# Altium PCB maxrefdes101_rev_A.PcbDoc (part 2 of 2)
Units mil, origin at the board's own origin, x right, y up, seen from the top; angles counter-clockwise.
Board outline 1192.91 x 1079.23 mil, 4 copper layers (Top Layer, Power Plane, Ground Plane, Bottom Layer), stack 32.372 mil thick; 87 components, 63 nets, 389 pads, 163 vias.
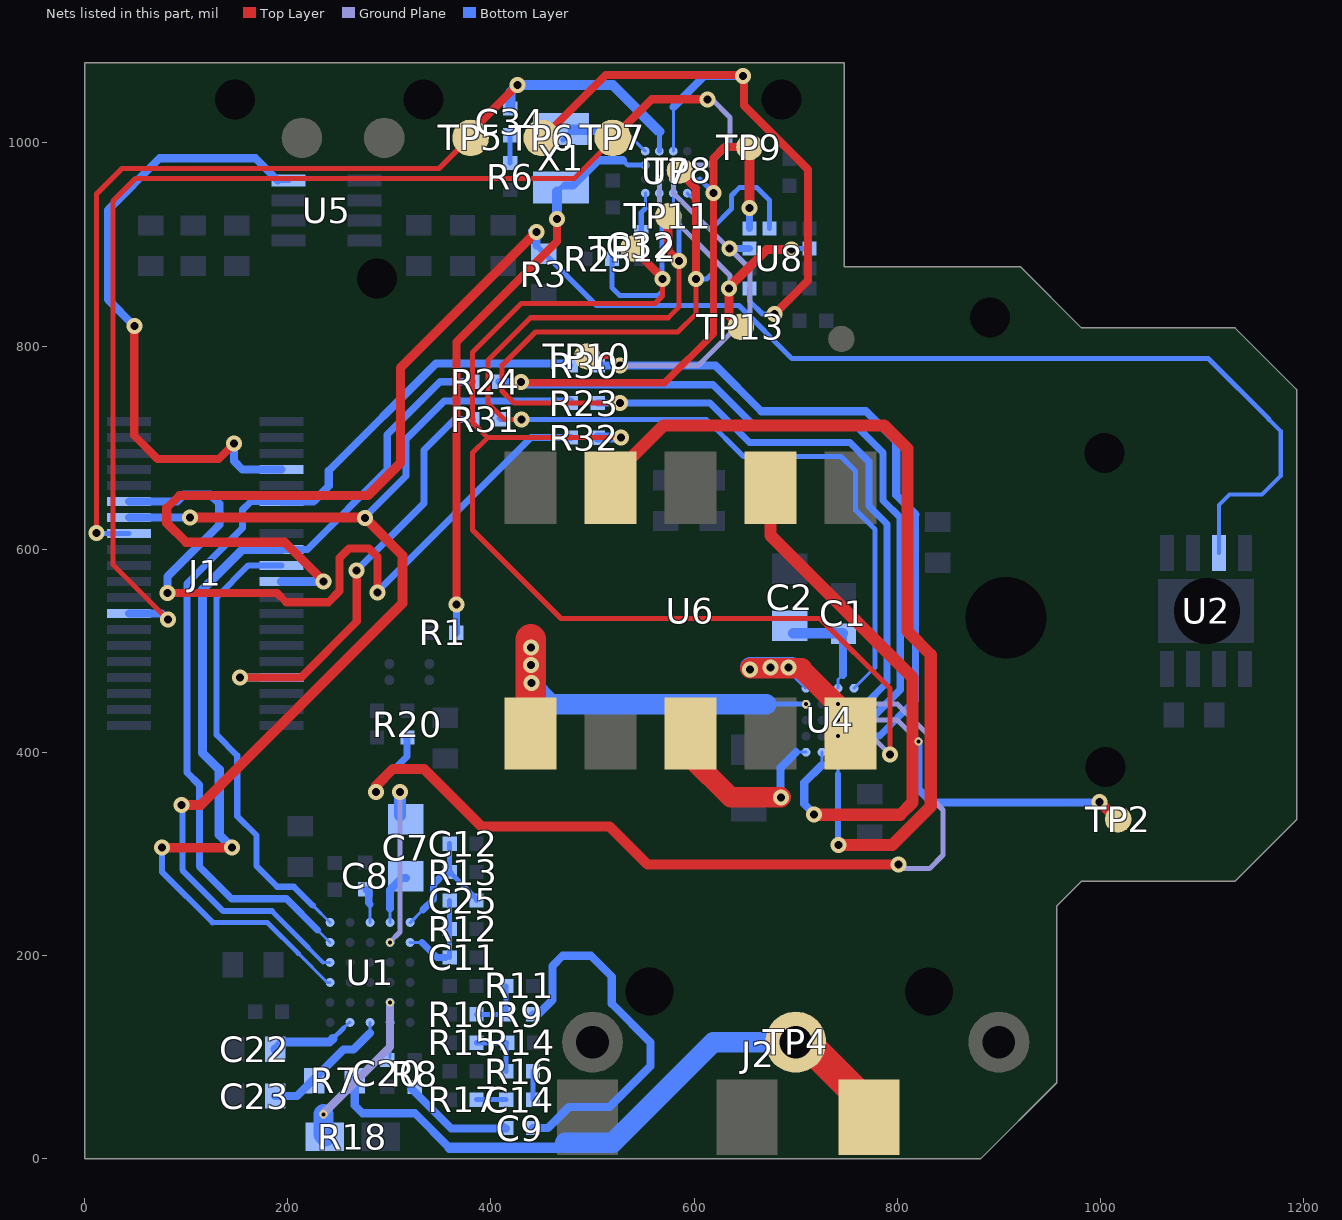
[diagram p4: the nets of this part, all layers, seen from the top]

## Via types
v1: diameter 15.75, hole 7.87, Top Layer to Bottom Layer, tented both sides, 114 vias
v2: diameter 8, hole 4, Ground Plane to Bottom Layer, 23 vias
v3: diameter 8, hole 4, Ground Plane to Bottom Layer, tented bottom, 14 vias
v4: diameter 11.81, hole 5.91, Ground Plane to Bottom Layer, tented bottom, 11 vias
v5: diameter 15.75/15.75/15.75/15.75 (per signal layer), hole 7.87, Top Layer to Bottom Layer, tented both sides, 1 vias

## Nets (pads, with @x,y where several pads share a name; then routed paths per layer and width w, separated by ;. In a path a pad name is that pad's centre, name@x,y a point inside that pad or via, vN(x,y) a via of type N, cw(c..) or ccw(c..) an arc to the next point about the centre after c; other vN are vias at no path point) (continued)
LED1: U4.D1 U6.3 | length 181.9
  Top Layer w20: U6.3@596.46,418.61 596.46,395.54 636,356 v1(685.39,356)
  Bottom Layer w3: 700.39,400.39 U4.D1@710.14,400.39
  Bottom Layer w8: v1@685,363 685,385 700.39,400.39
LED2_RESERVED: U4.C1 U6.7 | length 540.7
  Top Layer w12: U6.7@675.2,660.62 675.2,613.8 815,474 815,351 802.89,338.89 v1(717.89,338.89)
  Bottom Layer w3: 725.89,387.89 U4.C1@725.89,400.39
  Bottom Layer w8: v1@717.37,340.35 708.39,349.32 708.39,370.39 725.89,387.89
LED3_RESERVED: U4.B1 U6.9 | length 891.2
  Top Layer w5: U6.9@517.72,660.62 U6.9@517.72,669.72
  Top Layer w12: U6.9@517.72,669.72 570,722 787,722 810,699 810,519.37 833,496.37 833,347 795,309 v1(742,309)
  Bottom Layer w3: 741.64,378.7 U4.B1@741.64,399.39
  Bottom Layer w6: v1@741.64,309 741.64,378.7
LVL_SHIFT_PWDN: J1.7 U5.4 | length 622.2
  Top Layer w8: v1(49,820) 49,712 72,689 132.11,689 v1(147.12,704)
  Bottom Layer w5: U5.4@190.17,963.06 U5.4@201,963.06
  Bottom Layer w8: v1(49,820) 23,846 23,934 74,985 168.23,985 U5.4@190.17,963.06 ; v1(147.12,704) 147.12,686.88 155.24,678.76 J1.7@194,678.76
NetC1_1: C1.1 C2.1 U4.B5 | length 105
  Bottom Layer w3: U4.B5@741.64,463.38 741.64,471.87 746.39,476.62
  Bottom Layer w8: 746.39,476.62 C1.1@746.39,517.39
  Bottom Layer w10: C2.1@697.39,517.39 C1.1@746.39,517.39
NetC7_1: C7.1 U1.B6 | length 52.5
  Bottom Layer w3: U1.B6@300.7,232.81 300.7,246.48
  Bottom Layer w8: 300.7,246.48 300.7,264.83 312.26,276.39 C7.1@316.39,276.39
NetC7_2: C7.2 U1.B5 | length 175.5
  Ground Plane w5: v2@300.55,213.29 310.64,223.38 v1(310.64,361.39)
  Bottom Layer w12: C7.2@310.64,338.14 v1(310.64,361.39)
  other v2: 300.7,213.13
NetC8_1: C8.1 U1.C6 | length 34.3
  Bottom Layer w3: U1.C6@281.02,232.81 281.02,250.76
  Bottom Layer w7: C8.1@276.89,265.39 279.78,262.5 279.78,252 281.02,250.76
NetC9_1: C9.1 R9.1 | length 374.3
  Bottom Layer w8: C9.1@441.39,30.39 456.12,30.39 476.73,51 516.66,51 557,91.34 557,114.85 519,152.85 519,179.41 498.41,200 470.62,200 460.67,190.06 460.67,156.54 446.52,142.39 R9.1@441.39,142.39
NetC9_2: C9.2 R8.2 | length 113.3
  Bottom Layer w5: C9.2@412,33.39 C9.2@415,30.39
  Bottom Layer w8: R8.2@322.1,68.9 361,30 C9.2@415,30
NetC11_1: C11.1 C25.1 R12.1 U1.A5 | length 97.1
  Bottom Layer w3: U1.A5@320.39,213.13 332.18,213.13
  Bottom Layer w5: C11.1@359.39,198.39 R12.1@359.39,226.39 C25.1@359.39,254.39
  Bottom Layer w7: 332.18,213.13 346.92,198.39 C11.1@355.39,198.39
NetC12_1: C12.1 C25.2 R13.1 U1.A6 | length 135.7
  Bottom Layer w3: U1.A6@320.6,232.6 333,245
  Bottom Layer w5: C12.1@359.39,310.39 R13.1@359.39,282.39 385.78,256 C25.2@385.78,254.39
  Bottom Layer w7: 333,245 343.39,255.39 343.39,270.39 354.39,281.39 R13.1@360.39,281.39
NetC14_1: C14.1 R16.1 | length 28
  Bottom Layer w5: C14.1@441.39,58.39 R16.1@441.39,86.39
NetC14_2: C14.2 R17.2 | length 29.2
  Bottom Layer w5: R17.2@385.78,58.39 C14.2@415,58.39
NetC20_2: C20.2 U1.B1 | length 34.3
  Bottom Layer w3: C20.2@300.7,100.14 U1.B1@300.7,134.39
NetC22_2: C22.2 U1.D1 | length 84.6
  Bottom Layer w3: 255.04,129.04 260.39,134.39 U1.D1@261.33,134.39
  Bottom Layer w5: 244.35,118.35 255.04,129.04
  Bottom Layer w9: C22.2@187.62,108 194.62,115 241,115 244.35,118.35
NetC23_2: C23.2 R7.2 U1.C1 | length 129.5
  Bottom Layer w3: 281.02,124.02 U1.C1@281.02,134.39
  Bottom Layer w8: C23.2@187.62,62 209.16,62 254.97,107.81 264.81,107.81 281.02,124.02
NetC32_1: C32.1 U7.A4 | length 39.9
  Bottom Layer w3: 552,935.5 U7.A4@552,950.66
  Bottom Layer w5: C32.1@548,912.39 548,931.5 552,935.5
NetC34_2: C34.2 R6.1 | length 27.4
  Bottom Layer w5: R6.1@419,980.19 C34.2@419,1007.61
NetR1_2: R1.2 U7.A2 X1.2 | length 574
  Top Layer w8: v1(366,546) 366,804 465,903 v1(465,925)
  Bottom Layer w5: X1.2@465,952 X1.2@469,956 ; 530,983 534.78,978.22 U7.A2@552,978.22
  Bottom Layer w7: R1.2@365.97,518 v1@365.97,547.97
  Bottom Layer w8: X1.2@473,958 481,958 506,983 530,983
  Bottom Layer w10: v1(465,925) X1.2@465,952
NetR9_2: R9.2 R10.2 R11.2 | length 57.2
  Bottom Layer w5: R10.2@385.78,142.39 R9.2@415,142.39 R11.2@415,170.39
NetR14_1: R14.1 R15.2 R16.2 | length 57.2
  Bottom Layer w5: R15.2@385.78,114.39 R14.1@415.39,114.39 ; R16.2@415,86.39 R14.1@415,114
NetR18_1: R18.1 U1.B2 | length 160
  Ground Plane w8: v3@234.86,44.32 300.7,110.17 v2(300.7,154.07)
  Bottom Layer w5: R18.1@236.46,22 R18.1@237,22.54
  Bottom Layer w20: v3(235.2,43.98) 235.2,24.33 R18.1@237,22.54
NetR20_2: R20.2 U4.B4 | length 914.2
  Top Layer w10: v1(287,361) 287,367.39 303.61,384 334,384 390.61,327.39 516.61,327.39 554,290 v1(801,290)
  Ground Plane w5: v2(741.64,447.63) 800.19,447.63 833,414.82 833,355.39 845,343.39 845,299.11 831.65,285.76 805.24,285.76 v1(801,290)
  Bottom Layer w7: v1(287,361) 287,365.6 317.56,396.16 317.56,414.25 R20.2@316,415.81
  Bottom Layer w8: v1@798,290 v1(801,290)
NetTP2_TP: TP2.TP U4.B3 | length 343.8
  Top Layer w8: TP2.TP@1016,334.39 TP2.TP@1017.39,334.39
  Top Layer w10: v1(999.19,351.19) TP2.TP@1016,334.39
  Ground Plane w5: v2(741.64,431.89) 800.11,431.89 v3(821,411)
  Bottom Layer w8: v3(821,411) 821,363.89 833.89,351 v1@999.19,351
NetU7_A1: U7.A1 X1.1 | length 93.8
  Bottom Layer w3: 531,1013 U7.A1@552,992
  Bottom Layer w5: X1.1@471,1003 X1.1@481,1013
  Bottom Layer w10: X1.1@481,1013 531,1013
PD1: U4.D5 U6.5 | length 203.4
  Top Layer w5: v1@659,483 v1@660.15,481.85 ; U6.5@753.94,418.61 U6.5@753.94,434.06
  Top Layer w20: v1@655.15,483 706.15,483 ; 706.15,481.85 U6.5@753.94,434.06
  Bottom Layer w3: v1@691.32,482 709.93,463.39 U4.D5@710.14,463.38
  Bottom Layer w20: v1@655.16,484 v1@696.32,484
  other v1: 655.16,482 675,484 693,484
PD2: U4.D4 U6.1 | length 439.2
  Top Layer w30: U6.1@439.11,421.77 439.11,511.37
  Bottom Layer w5: v1(439.64,503.23) v1@439.95,502.92 ; 671.11,447.63 v2(710.14,447.63)
  Bottom Layer w20: v1(439.64,503.23) 439.64,467.1 459.11,447.63 671.11,447.63 ; v1(439.95,468.42) v1@439.95,502.92
  other v1: 439.64,486.23
PPG_INT: J1.12 R32.2 | length 748.9
  Top Layer w8: v1(81.77,557) 189.61,557 198.61,548 240,548 251,559 251,591.61 260.39,601 280,601 288.26,592.74 v1(288.26,557.62)
  Bottom Layer w7: v1(288.26,557.62) 287.24,557.62 439.62,710 R32.2@478.81,710
  Bottom Layer w8: J1.12@44,647.26 91.26,647.26 98,654 123.6,654 132.6,645 132.6,624.11 81.77,573.27 81.77,558.87 v1@81,558.11
PS00_ACCEL_CS: TP6.TP U7.C1 U8.10 | length 663.4
  Top Layer w8: TP6.TP@451,1005 513,1067 645,1067 649,1063 649,1037 712,974 712,864.61 v1(679,831.61)
  Bottom Layer w3: U7.C1@579.56,992 579.56,1035.56
  Bottom Layer w5: U8.10@654.39,856.94 654.39,844.61 667.39,831.61 v1(679,831.61)
  Bottom Layer w8: 579.56,1035.56 610,1066 v1(648,1066)
PS01_MFIO: J1.26 TP7.TP U7.C2 | length 1223.2
  Top Layer w5: v5@81.5,531.5 28,585 28,942.88 50.12,965 482,965 519,1002 TP7.TP@519,1006
  Top Layer w8: TP7.TP@520,1005 558,1043 609,1043 v1@611,1045
  Ground Plane w5: v2(579.56,978.22) 614.25,978.22 635.39,999.35 635.39,1025.21 617.3,1043.3 v1@613,1039
  Bottom Layer w8: J1.26@44,537.02 75.98,537.02 v5(82,531)
  other v1: 613,1043
PS04_SPI0_MISO: R24.1 TP9.TP U4.A3 U7.D3 U8.1 | length 1238.1
  Top Layer w5: v1@651,936 654.39,939.39 654.39,937.34 v1(654.39,936)
  Top Layer w7: v1@431.81,764 571,764 619,812 v1(619,951)
  Top Layer w8: v1(619,951) 618,951 619,952 619,985 630,996 TP9.TP@654.39,996 ; v1@653.36,938.36 v1@654.39,937.34
  Top Layer w10: v1@654.39,939.39 TP9.TP@654.39,996
  Bottom Layer w3: U7.D3@593.34,964.44 605.83,964.44 ; U4.A3@757.39,431.89 772.89,431.89
  Bottom Layer w5: 605.83,964.44 v1@618,952.27
  Bottom Layer w7: R24.1@408.19,765 v1(429.81,765) ; v1@432.81,762 618.72,762 657.72,723 758.2,723 786,695.2 786,648.28 802.88,631.4 802.88,461.88 772.89,431.89 ; U8.1@654.39,916 v1(654.39,936)
PS05_SPI0_MOSI: R23.1 TP8.TP U4.A4 U7.D4 U8.2 | length 1379.9
  Top Layer w5: v1(527,744) 423,744 411,756 411,781 444,814 584,814 602,832 v1(602,866.2)
  Top Layer w8: TP8.TP@586.33,979 586.33,970.92 602,955.25 v1(602,866.2)
  Bottom Layer w3: U7.D4@593.34,950.66 601.39,942.61 ; U4.A4@757.39,447.63 768.63,447.63
  Bottom Layer w5: v1@598,867 v1@601.39,867 ; v1@601.39,866.2 v1@601.39,867 ; 601.39,911.12 v1@601.39,867 ; 601.39,942.61 v1@601.39,867 ; v1(602,866.2) 612.44,866.2 618.72,872.49 618.72,917.18 636.82,935.28 636.82,948.29 644.54,956 662,956 674.07,943.93 U8.2@674.07,916
  Bottom Layer w7: R23.1@505.19,744 615.63,744 654.54,705.1 753.42,705.1 772.23,686.29 772.23,642.77 790,625 790,469 768.63,447.63
PS06_SPI0_SCK: R30.1 TP10.TP U4.A2 U7.C3 U8.12 | length 1029.8
  Top Layer w5: TP10.TP@495,790 518.07,790 v1(527.07,781)
  Ground Plane w5: v1(527.07,781) 604.01,781 655,832 655,875.91 v1(634.84,896.07) ; v2(579.56,964.44) 579.56,950.9 v1@634.61,895.85
  Bottom Layer w3: U4.A2@757.39,416.14 770.64,416.14
  Bottom Layer w7: v1@634.84,896.31 U8.12@654.39,896.31 ; 770.39,416.39 782.39,416.39 818,452 818,634.51
  Bottom Layer w8: R30.1@506,781 v1(527.07,781) 621,781 666.06,735.94 769.06,735.94 799,706 799,653.51 818,634.51
PS07_PPG_CS: R31.1 TP11.TP U4.A5 U7.C4 | length 1060.9
  Top Layer w5: v1(430,728) 413,728 397,744 397,786 439,828 574.56,828 585,838.44 585,881.56 v1@581.56,885
  Top Layer w8: TP11.TP@574.56,928 574.56,894.44 v1(585,884)
  Bottom Layer w3: 579.56,934.76 U7.C4@579.56,950.66 ; U4.A5@757.39,463.38 778,483.99
  Bottom Layer w5: R31.1@408.19,729 409.2,728 612,728 648.65,691.35 744.49,691.35 759,676.83 759,638.74 778,619.74 778,483.99 ; 579.56,934.76 585,929.32 585,889 v1@580,884
PS08_PPG_INT: R25.2 R32.1 TP12.TP U4.B2 U7.B4 | length 1388.6
  Top Layer w5: v1(528,710) 397,710 ; v1(569,866.19) v1@569,867.07 ; v1@570.19,864.19 569,863 569,849.44 561.56,842 430,842 382,794 382,725 397,710 ; v1(793,398) 793,463 724,532 469,532 382,619 382,695 397,710
  Top Layer w8: TP12.TP@540,896.07 v1@569,867.07
  Ground Plane w5: v2(741.64,416.14) 774.86,416.14 v1(793,398)
  Bottom Layer w3: U7.B4@565.78,950.66 565.78,930.65 568.46,927.96
  Bottom Layer w5: R25.2@519.19,887 519.19,857.57 526.76,850 564.93,850 569,854.07 v1(569,866.19) ; 568.46,927.96 568.46,867.92 v1@569,867.39
  Bottom Layer w10: R32.1@505.19,710 v1(528,710)
PS09_ACCEL_INT: TP13.TP U7.B3 U8.5 | length 274.5
  Top Layer w9: TP13.TP@646,819 634.39,830.61 634.39,858.05 671.34,895 v1(696,895)
  Ground Plane w5: v2(565.78,964.44) 565.78,939.26 635.37,869.67 v1@635.37,856.94
  Bottom Layer w5: v1@696,896.31 U8.5@713.44,896.31
  other v1: 634.39,856.94
PS_RESET: C34.1 J1.16 TP5.TP U7.B1 | length 1028
  Top Layer w5: v1(11.73,616) 11.73,949.73 37,975 349,975 374.5,1000.5 TP5.TP@378.5,1000.5 ; v1(426,1057) v1@430,1057
  Top Layer w8: TP5.TP@376,1007 v1(426,1057)
  Bottom Layer w5: v1@16,615.76 J1.16@44,615.76 ; U7.B1@565.78,992 565.78,1011.22
  Bottom Layer w10: C34.1@419.26,1034 419.26,1050.26 v1(426,1057) 520,1057 565.78,1011.22
SPI_ECG_SS: J1.19 U1.E6 | length 453.2
  Bottom Layer w3: 224.8,249.38 225.09,249.38 U1.E6@241.65,232.81
  Bottom Layer w6: J1.19@194,584.27 161.34,584.27 130,552.93 130,417.39 150.39,397 150.39,337.39 169.39,318.39 169.39,288.19 189.58,268 206.17,268 224.8,249.38
SPI_MISO: J1.17 R24.2 U1.E3 | length 940.1
  Top Layer w9: v1(76.39,306.39) v1(145.4,306.39)
  Bottom Layer w3: 210.39,202.39 239.02,173.76 U1.E3@241.65,173.76
  Bottom Layer w5: 125.96,232.81 179.96,232.81 210.39,202.39
  Bottom Layer w6: v1(76.39,306.39) 76.39,282.39 125.96,232.81
  Bottom Layer w7: J1.17@194,600.02 219.38,600.02 297.96,678.6 297.96,712.96 350,765 R24.2@381.81,765
  Bottom Layer w9: v1(145.4,306.39) 132.6,319.19 132.6,383.25 116,399.85 116,560.39 155.63,600.02 J1.17@194,600.02
SPI_MOSI: J1.14 R23.2 U1.E4 | length 1151.2
  Top Layer w10: v1(95.39,348.39) 114.39,348.39 313,547 313,594 v1(276,631) ; v1(104,631.51) v1@276,631.51
  Bottom Layer w3: 234.82,193.44 U1.E4@241.65,193.44
  Bottom Layer w4: 220.39,207.87 234.82,193.44
  Bottom Layer w5: 184.26,244 220.39,207.87
  Bottom Layer w6: v1@96.39,346.39 96.39,284.39 136.78,244 184.26,244
  Bottom Layer w7: v1@276,628 276,631.8 316.39,672.19 316.39,708.39 354,746 R23.2@478.81,746
  Bottom Layer w8: J1.14@44,631.51 v1(104,631.51)
SPI_PPG_SS: J1.33 R31.2 | length 435.4
  Top Layer w8: v1(152.93,474) 213,474 268,529 v1@268,579.22
  Bottom Layer w7: v1(267.86,579.22) 334,645.36 334,697.75 364.25,728 R31.2@381.81,728
  Bottom Layer w8: v1@152.96,474.03 J1.33@194,474.03
SPI_SCLK: J1.11 R30.2 U1.E5 | length 929.1
  Bottom Layer w3: 229.39,225.39 U1.E5@241.65,213.13
  Bottom Layer w7: J1.11@194,647.26 163.79,647.26 155.63,639.1 155.63,621 101,566.37 101,380.33 113,368.33 113,287.78 144.66,256.12 198.66,256.12 229.39,225.39
  Bottom Layer w8: J1.11@194,647.26 225.26,647.26 240.39,662.39 240.39,677.39 346,783 475,783 R30.2@477,781
TEMP_OS: J1.21 R3.2 U2.3 | length 1764.6
  Top Layer w8: 81,640.61 93.39,653
  Top Layer w9: 81,640.61 81,626 100,607 197,607 236,568 v1@238.51,568 ; 93.39,653 279,653 311,685 311,778.61 v1(444.78,912.39)
  Bottom Layer w4: U2.3@1116.8,596.48 1116.8,643.8 1127,654 1159,654 1177.39,672.39 1177.39,716.61 1166,728
  Bottom Layer w5: v1@439.19,913.81 v1@446.58,913.81 ; R3.2@444.78,899.22 504,840 644.18,840 696.18,788 1106,788 1166,728
  Bottom Layer w8: R3.2@444.78,899.22 v1(444.78,912.39)
  Bottom Layer w9: J1.21@194,568.52 v1@238.51,568.52
  other v1: 235,568.52
VCM: J2.1 R7.1 TP4.TP | length 620.9
  Top Layer w30: TP4.TP@710,115 769,56 769,58 767,56 J2.1@767,42
  Bottom Layer w8: R7.1@266,77 266,52.76 273.76,45 325.13,45 359.13,11
  Bottom Layer w10: 359.13,11 468,11 473,16
  Bottom Layer w20: 473,16 520,16 619,115 TP4.TP@700,115
pads on no net: J1.1 J1.5 J1.6 J1.8 J1.15 J1.20 J1.22 J1.23 J1.27 J1.28 J1.29 J1.30 J1.31 J1.32 J1.34 J1.35 J1.36 J1.37 J2.0 U1. U1.C2 U2.9 U4. U6.6 U6.10 U7. U8.6

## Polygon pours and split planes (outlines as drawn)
1V8 on Power Plane "PLANE_1V8" (solid, pour order 4): 0,0 509.73,0.31 509.73,226.39 525.73,242.39 840,242.39 840,878.39 812.39,878.39 748,878.39 748,1078.23 0,1079.23
5V on Power Plane "PLANE_5V" (solid, remove dead copper, pour order 2): 57.98,702.77 157.75,603 476.24,603 710.51,368.74 710.51,344.48 735,320 776.26,320 804.43,348.17 804.43,465.09 620,649.51 620,718.21 548.83,789.39 320.57,789.39 256.77,725.59 226.19,725.59 175.78,776 82,776 57.98,751.98
GND on Ground Plane "PLANE_GROUND" (solid, remove dead copper, pour order 6): 0,0 772,0 836.39,64.39 836.39,1079.23 0,1079.23
GND on Bottom Layer "COMPONENT_GND" (solid, remove dead copper, pour order 8): 0,0 825,0 836,11 836,878.39 748.61,878.39 748,879 748,1079 0,1079

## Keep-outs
Keep-Out Layer:
  lines w1: 0,0 0,1079.23 748,1079.23 748,878.39 920.91,878.39 981.39,817.91 1132.39,817.91 1192.91,757.39 1192.91,333.91 1132.39,273.39 981.39,273.39 957,249 957,75 882,0 0,0 ; 752.39,881.39 1119.39,881.39 1119.39,1079.23 752.39,1079.23 752.39,881.39

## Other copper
Top Layer:
  text "Top Layer" at 2872,76 h60
Power Plane:
  pour cut-out: 836.39,0.31 836.39,1079.23 1192.91,1079.23 1192.91,714.39 1192.91,0
  text "Power Plane" at 2883,-21 h60
Ground Plane:
  pour cut-out: 748,878 748,1079 1119.39,1079 1119,1078.61 1119,881.39
  pour cut-out: 761,-0.17 761,166 835.39,166 835.39,1 836.39,0
  pour cut-out: 499,500.5 499,461.33 504.33,456 619.48,456 634.95,471.48 634.85,494.14 623.37,505.62 503.55,505.62
  text "Ground Plane" at 2878,-102 h60
Bottom Layer:
  pour cut-out: 838.48,367 838.48,712 837.48,713 1192,713 1192,367
  text "Bottom Layer" at 2882,-190 h60

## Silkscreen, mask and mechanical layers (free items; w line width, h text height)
Top Overlay:
  drawing of 1575 lines, arcs and shapes, not listed
  text "REV-A" at 70,846.46 h70 r90
  text "TM" at 240.49,823.56 h25 r90
  text "Top Silkscreen" at 2875,173 h60
  text "ECGP" at 521,165 h55 r90
  text "ECGN" at 918,165 h55 r90
  text "VCM" at 718,164 h55 r90
  text "MAXREFDES101#" at 70,27 h70 r90
Bottom Overlay:
  circle w10: c337,118 r4.47
  circle w10: c536,1031 r4.24
  circle w10: c631,929 r4.24
  circle w10: c801,382 r4.47
  text "Bottom Silkscreen" at 2883,-281 h60
Mechanical 1:
  drawing of 295 lines, arcs and shapes, not listed
  text "Layer" at 2963.09,1892 h60
  text "Name" at 3373,1892 h60
  text "Material" at 4302.74,1892 h60
  text "Thickness" at 5162.51,1892 h60
  text "Constant" at 5812.35,1892 h60
  text "Board Layer Stack" at 6382.21,1892 h60
  text "1" at 2963.09,1772 h60
  text "Top Overlay" at 3373,1772 h60
  text "2" at 2963.09,1652 h60
  text "Top Solder" at 3373,1652 h60
  text "Solder Resist" at 4302.74,1652 h60
  text "0.40mil" at 5162.51,1652 h60
  text "3.5" at 5812.35,1652 h60
  text "3" at 2963.09,1532 h60
  text "Top Layer" at 3373,1532 h60
  text "Copper" at 4302.74,1532 h60
  text "1.40mil" at 5162.51,1532 h60
  text "4" at 2963.09,1412 h60
  text "Dielectric1" at 3373,1412 h60
  text "FR-4" at 4302.74,1412 h60
  text "6.89mil" at 5162.51,1412 h60
  text "4.2" at 5812.35,1412 h60
  text "5" at 2963.09,1292 h60
  text "Power Plane" at 3373,1292 h60
  text "Copper" at 4302.74,1292 h60
  text "1.40mil" at 5162.51,1292 h60
  text "6" at 2963.09,1172 h60
  text "Dielectric2" at 3373,1172 h60
  text "FR-4" at 4302.74,1172 h60
  text "12.99mil" at 5162.51,1172 h60
  text "4.2" at 5812.35,1172 h60
  text "7" at 2963.09,1052 h60
  text "Ground Plane" at 3373,1052 h60
  text "Copper" at 4302.74,1052 h60
  text "1.40mil" at 5162.51,1052 h60
  text "8" at 2963.09,932 h60
  text "Dielectric5" at 3373,932 h60
  text "FR-4" at 4302.74,932 h60
  text "6.89mil" at 5162.51,932 h60
  text "4.2" at 5812.35,932 h60
  text "9" at 2963.09,812 h60
  text "Bottom Layer" at 3373,812 h60
  text "Copper" at 4302.74,812 h60
  text "1.40mil" at 5162.51,812 h60
  text "10" at 2963.09,692 h60
  text "Bottom Solder" at 3373,692 h60
  text "Solder Resist" at 4302.74,692 h60
  text "0.40mil" at 5162.51,692 h60
  text "3.5" at 5812.35,692 h60
  text "11" at 2963.09,572 h60
  text "Bottom Overlay" at 3373,572 h60
Mechanical 11:
  lines w1: 0,0 0,38 0,1079.23 748,1079.23 748,878.39 920.91,878.39 981.39,817.91 1132.39,817.91 1192.91,757.39 1192.91,333.91 1132.39,273.39 981.39,273.39 957,249 957,75 882,0 0,0
  text "Board Outline" at 2884,-371 h60
Mechanical 16:
  circle w25: c7712.68,-99.1 r158.12
  lines w5: -1405,1145 -1205,1145 ; -1397,3760 -1197,3760 ; -1397,6135 -1197,6135 ; 1095,-1230 1095,-1030 ; 1095,8070 1095,8270 ; 3595,-1230 3595,-1030 ; 3595,8070 3595,8270 ; 6095,-1230 6095,-1030 ; 6095,8070 6095,8270 ; 8595,-1230 8595,-1030 ; 8595,8070 8595,8270 ; 8895,-730 13395,-730 ; 8895,-430 13395,-430 ; 8895,-130 10395,-130 ; 10395,-1030 10395,-430 10395,170 ; 11095,-1230 11095,-1030 ; 11095,8070 11095,8270 ; 12495,-1030 12495,-430 ; 13395,1145 13595,1145 ; 13395,3520 13595,3520 ; 13395,5895 13595,5895 ; 8895,-1030 7495,-1030 7495,170 8895,170 ; 8895,-1030 13395,-1030 ; 8895,-1030 8895,170 ; 8895,170 10395,170 ; 10395,170 13395,170 13395,-1030 ; 13395,-1030 13395,8070 -1205,8070 -1205,-1030 13395,-1030 ; -1405,-1230 -1405,8270 13595,8270 13595,-1230 -1405,-1230
  text "1" at -173.66,8140 h70
  text "2" at 2322,8140 h70
  text "3" at 4811.34,8140 h70
  text "4" at 7318.01,8140 h70
  text "5" at 9817,8140 h70
  text "6" at 12322,8140 h70
  text "A" at -1330,6997 h70
  text "A" at 13470,6997 h70
  text "B" at -1322,4857 h70
  text "B" at 13470,4617 h70
  text "C" at -1330,2242 h70
  text "C" at 13470,2242 h70
  text "ENGINEER:" at 8945,70 h45
  text "TITLE:" at 10445,70 h45
  text "maxim" at 7927.69,-62.27 h225
  text "MAXREFDES101#" at 10544,-80 h118.11
  text "D" at -1330,-128 h70
  text "D" at 13470,-128 h70
  text "T" at 8717.69,-212.27 h100
  text "M" at 8767.69,-212.27 h100
  text "integrated" at 7927.69,-222.27 h225
  text "PCB DESIGNER:" at 8945,-225 h45
  text "Maxim Integrated" at 7602.69,-437.27 h80
  text "DATE:" at 8945,-530 h45
  text "PART NO.:" at 10445,-530 h45
  text "REV:" at 12545,-530 h45
  text "160 Rio Robles" at 7602.69,-592.27 h80
  text "A" at 12721,-633 h59.06
  text "4/5/2018" at 8976,-647 h59.06
  text "San Jose, CA 95134" at 7602.69,-707.27 h80
  text "FILE NAME:" at 8945,-830 h45
  text "DWG NO:" at 10445,-830 h45
  text "SCALE:" at 12545,-830 h45
  text "(408) 733-7600" at 7597.69,-852.27 h80
  text "MAXREFDES101_A" at 8995,-950 h59.06
  text "1" at -173.66,-1160 h70
  text "2" at 2322,-1160 h70
  text "3" at 4811.34,-1160 h70
  text "4" at 7318.01,-1160 h70
  text "5" at 9817,-1160 h70
  text "6" at 12322,-1160 h70
Drill Drawing:
  circle w10: c1222.78,3239.71 r33.17
  lines w10: 1189.61,2626.04 1206.2,2626.04 1206.2,2609.46 1239.37,2609.46 1239.37,2626.04 1255.96,2626.04 1255.96,2659.21 1239.37,2659.21 1239.37,2675.8 1206.2,2675.8 1206.2,2659.21 1189.61,2659.21 1189.61,2626.04 ; 1189.61,2758.73 1255.96,2758.73 1255.96,2825.07 1189.61,2825.07 1189.61,2758.73 ; 1189.61,2908 1222.78,2924.59 1255.96,2908 1239.37,2941.17 1255.96,2974.34 1222.78,2957.76 1189.61,2974.34 1206.2,2941.17 1189.61,2908 ; 1189.61,3073.86 1206.2,3073.86 1222.78,3057.27 1239.37,3073.86 1255.96,3073.86 1239.37,3090.44 1255.96,3107.03 1239.37,3107.03 1222.78,3123.61 1206.2,3107.03 1189.61,3107.03 1206.2,3090.44 1189.61,3073.86 ; 1189.61,3388.99 1222.78,3355.81 1255.96,3388.99 1222.78,3422.16 1189.61,3388.99 ; 1189.61,3571.43 1255.96,3571.43 1222.78,3505.09 1189.61,3571.43 ; 1189.61,3654.36 1255.96,3654.36 1255.96,3720.7 1189.61,3720.7 1189.61,3654.36 ; 1189.61,3803.63 1189.61,3820.21 1206.2,3836.8 1189.61,3853.39 1189.61,3869.97 1206.2,3869.97 1222.78,3853.39 1239.37,3869.97 1255.96,3869.97 1255.96,3853.39 1239.37,3836.8 1255.96,3820.21 1255.96,3803.63 1239.37,3803.63 1222.78,3820.21 1206.2,3803.63 1189.61,3803.63 ; 1202.88,3667.63 1242.69,3667.63 1242.69,3707.43 1202.88,3707.43 1202.88,3667.63
  lines w15: 1130.1,2564.68 12964.75,2564.68 ; 1130.1,3908.12 12964.75,3908.12 ; 1678.45,2415.4 1678.45,4057.39 ; 2265.53,2415.4 2265.53,4057.39 ; 3359.97,2415.4 3359.97,4057.39 ; 3863.54,2415.4 3863.54,4057.39 ; 4593.93,2415.4 4593.93,4057.39 ; 6255.42,2415.4 6255.42,4057.39 ; 6842.56,2415.4 6842.56,4057.39 ; 7584.89,2415.4 7584.89,4057.39 ; 8271.45,2415.4 8271.45,4057.39 ; 9121.22,2415.4 9121.22,4057.39 ; 10448.5,2415.4 10448.5,4057.39 ; 11775.79,2415.4 11775.79,4057.39 ; 1130.1,2415.4 12964.75,2415.4 12964.75,4057.39 1130.1,4057.39 1130.1,2415.4
  text "Symbol" at 1219.66,3952.9 h71.65
  text "Count" at 1723.23,3952.9 h71.65
  text "Hole Size" at 2310.31,3952.9 h71.65
  text "Plated" at 3404.75,3952.9 h71.65
  text "Hole Type" at 3908.32,3952.9 h71.65
  text "Drill Layer Pair" at 4638.71,3952.9 h71.65
  text "Via/Pad" at 6300.2,3952.9 h71.65
  text "Pad Shape" at 6887.34,3952.9 h71.65
  text "Template" at 7629.67,3952.9 h71.65
  text "Description" at 8316.23,3952.9 h71.65
  text "Hole Tolerance (+)" at 9166,3952.9 h71.65
  text "Hole Tolerance (-)" at 10493.29,3952.9 h71.65
  text "Hole Length" at 11820.57,3952.9 h71.65
  text "1" at 1723.23,3803.63 h59.71
  text "1.651mm (65.00mil)" at 2310.31,3803.63 h59.71
  text "PTH" at 3404.75,3803.63 h59.71
  text "Rectangle" at 3908.32,3803.63 h59.71
  text "Top Layer - Bottom Layer" at 4638.71,3803.63 h59.71
  text "Pad" at 6300.2,3803.63 h59.71
  text "Rectangle" at 6887.34,3803.63 h59.71
  text "s0h165_254" at 7629.67,3803.63 h59.71
  text "2.540mm (100.00mil)" at 11820.57,3803.63 h59.71
  text "1" at 1723.23,3654.36 h59.71
  text "2.032mm (80.00mil)" at 2310.31,3654.36 h59.71
  text "PTH" at 3404.75,3654.36 h59.71
  text "Rectangle" at 3908.32,3654.36 h59.71
  text "Top Layer - Bottom Layer" at 4638.71,3654.36 h59.71
  text "Pad" at 6300.2,3654.36 h59.71
  text "Rectangle" at 6887.34,3654.36 h59.71
  text "s0h203_533" at 7629.67,3654.36 h59.71
  text "5.334mm (210.00mil)" at 11820.57,3654.36 h59.71
  text "2" at 1723.23,3505.09 h59.71
  text "1.000mm (39.37mil)" at 2310.31,3505.09 h59.71
  text "PTH" at 3404.75,3505.09 h59.71
  text "Rectangle" at 3908.32,3505.09 h59.71
  text "Top Layer - Bottom Layer" at 4638.71,3505.09 h59.71
  text "Pad" at 6300.2,3505.09 h59.71
  text "Rectangle" at 6887.34,3505.09 h59.71
  text "s0h100_813" at 7629.67,3505.09 h59.71
  text "8.128mm (320.00mil)" at 11820.57,3505.09 h59.71
  text "2" at 1723.23,3355.81 h59.71
  text "1.200mm (47.24mil)" at 2310.31,3355.81 h59.71
  text "NPTH" at 3404.75,3355.81 h59.71
  text "Round" at 3908.32,3355.81 h59.71
  text "Top Layer - Bottom Layer" at 4638.71,3355.81 h59.71
  text "Pad" at 6300.2,3355.81 h59.71
  text "Rounded" at 6887.34,3355.81 h59.71
  text "c0hn120" at 7629.67,3355.81 h59.71
  text "-" at 11820.57,3355.81 h59.71
  text "3" at 1723.23,3206.54 h59.71
  text "0.813mm (32.00mil)" at 2310.31,3206.54 h59.71
  text "PTH" at 3404.75,3206.54 h59.71
  text "Round" at 3908.32,3206.54 h59.71
  text "Top Layer - Bottom Layer" at 4638.71,3206.54 h59.71
  text "Pad" at 6300.2,3206.54 h59.71
  text "Rounded" at 6887.34,3206.54 h59.71
  text "c152h81" at 7629.67,3206.54 h59.71
  text "-" at 11820.57,3206.54 h59.71
  text "5" at 1723.23,3057.27 h59.71
  text "1.000mm (39.37mil)" at 2310.31,3057.27 h59.71
  text "PTH" at 3404.75,3057.27 h59.71
  text "Round" at 3908.32,3057.27 h59.71
  text "Top Layer - Bottom Layer" at 4638.71,3057.27 h59.71
  text "Pad" at 6300.2,3057.27 h59.71
  text "Rounded" at 6887.34,3057.27 h59.71
  text "c0h100" at 7629.67,3057.27 h59.71
  text "-" at 11820.57,3057.27 h59.71
  text "11" at 1723.23,2908 h59.71
  text "0.150mm (5.91mil)" at 2310.31,2908 h59.71
  text "PTH" at 3404.75,2908 h59.71
  text "Round" at 3908.32,2908 h59.71
  text "Ground Plane - Bottom Layer" at 4638.71,2908 h59.71
  text "Via" at 6300.2,2908 h59.71
  text "Rounded" at 6887.34,2908 h59.71
  text "v30h15mx0" at 7629.67,2908 h59.71
  text "-" at 11820.57,2908 h59.71
  text "37" at 1723.23,2758.73 h59.71
  text "0.102mm (4.00mil)" at 2310.31,2758.73 h59.71
  text "PTH" at 3404.75,2758.73 h59.71
  text "Round" at 3908.32,2758.73 h59.71
  text "Ground Plane - Bottom Layer" at 4638.71,2758.73 h59.71
  text "Via" at 6300.2,2758.73 h59.71
  text "Rounded" at 6887.34,2758.73 h59.71
  text "(Mixed)" at 7629.67,2758.73 h59.71
  text "-" at 11820.57,2758.73 h59.71
  text "115" at 1723.23,2609.46 h59.71
  text "0.200mm (7.87mil)" at 2310.31,2609.46 h59.71
  text "PTH" at 3404.75,2609.46 h59.71
  text "Round" at 3908.32,2609.46 h59.71
  text "Top Layer - Bottom Layer" at 4638.71,2609.46 h59.71
  text "Via" at 6300.2,2609.46 h59.71
  text "Rounded" at 6887.34,2609.46 h59.71
  text "(Mixed)" at 7629.67,2609.46 h59.71
  text "-" at 11820.57,2609.46 h59.71
  text "177 Total" at 1723.23,2460.19 h59.71
  text "Slot definitions :" at 1219.66,2315.82 h59.71
  text "Routed Path Length" at 2247.47,2315.82 h59.71
  text "= Calculated from tool start centre position to tool end centre position." at 3344.92,2315.82 h59.71
  text "Hole Length" at 2247.47,2216.23 h59.71
  text "= Routed Path Length + Tool Size = Slot length as defined in the PCB layout" at 2937.04,2216.23 h59.71
Mechanical 31:
  circle w7: c741.64,431.89 r88.44
  circle w7: c283,189 r88.44
  circle w7: c569.95,978.22 r88.44
  lines w8: 2177.47,2643.4 2181.38,2637.1 2182.95,2629.75 2180.6,2622.4
  lines w10: 290,277 290,448 290,1136 544,1390 ; 569,1067 569,1397 ; 594,1391 742,1243 742,520 ; 2847,-538 2847,255 6445,255 6445,-538 2847,-538
  text "NOTES" at -997,7599 h196.85
  text "ALL MEASUREMENTS ARE IN INCHES /  / BOARD MATERIAL TO BE MULTI FUNCTIONAL FR4 EPOXY GLASS / LAMINATE AND SHALL MEET OR EXCEED MIL-P-13949 COLOR - NATURAL /  / OVERALL BOARD THICKNESS TO BE 0.31 +/-10 MEASURED FROM COPPER TO COPPER" at -840,6233 h196.85
  text "PROCESS NOTES" at -1017,5702 h196.85
  text "APPLY SOLDERMASK. BOTH SIDES. OVER BARE COPPER (SMOBC) /  / COLOR : BLACK /  / SOLDERMASK SHALL CONFORM IPC-SM-840. CLASS H / FABRICATION VENDOR IS ALLOWED TO ADJUST SOLDERMASK FEATURES AS NEEDED AS LONG AS SOLDERMAK / DAMS ARE MAINTAINED  BETWEEN ALL SMD PADS" at -860,4336 h196.85
  text "MICRO VIA IN PAD (STACKED MICRO VIA) /  / PLATED AND PLANARIZED. WLP (BGA) MOUNTING PAD" at -583,1396 h196.85
  text "Silkscreen For Top Layer : WHITE" at 4062,-28 h60
  text "Silkscreen For Bottom Layer : WHITE" at 4074,-167 h60
  text "Notes" at 2882,-480 h60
